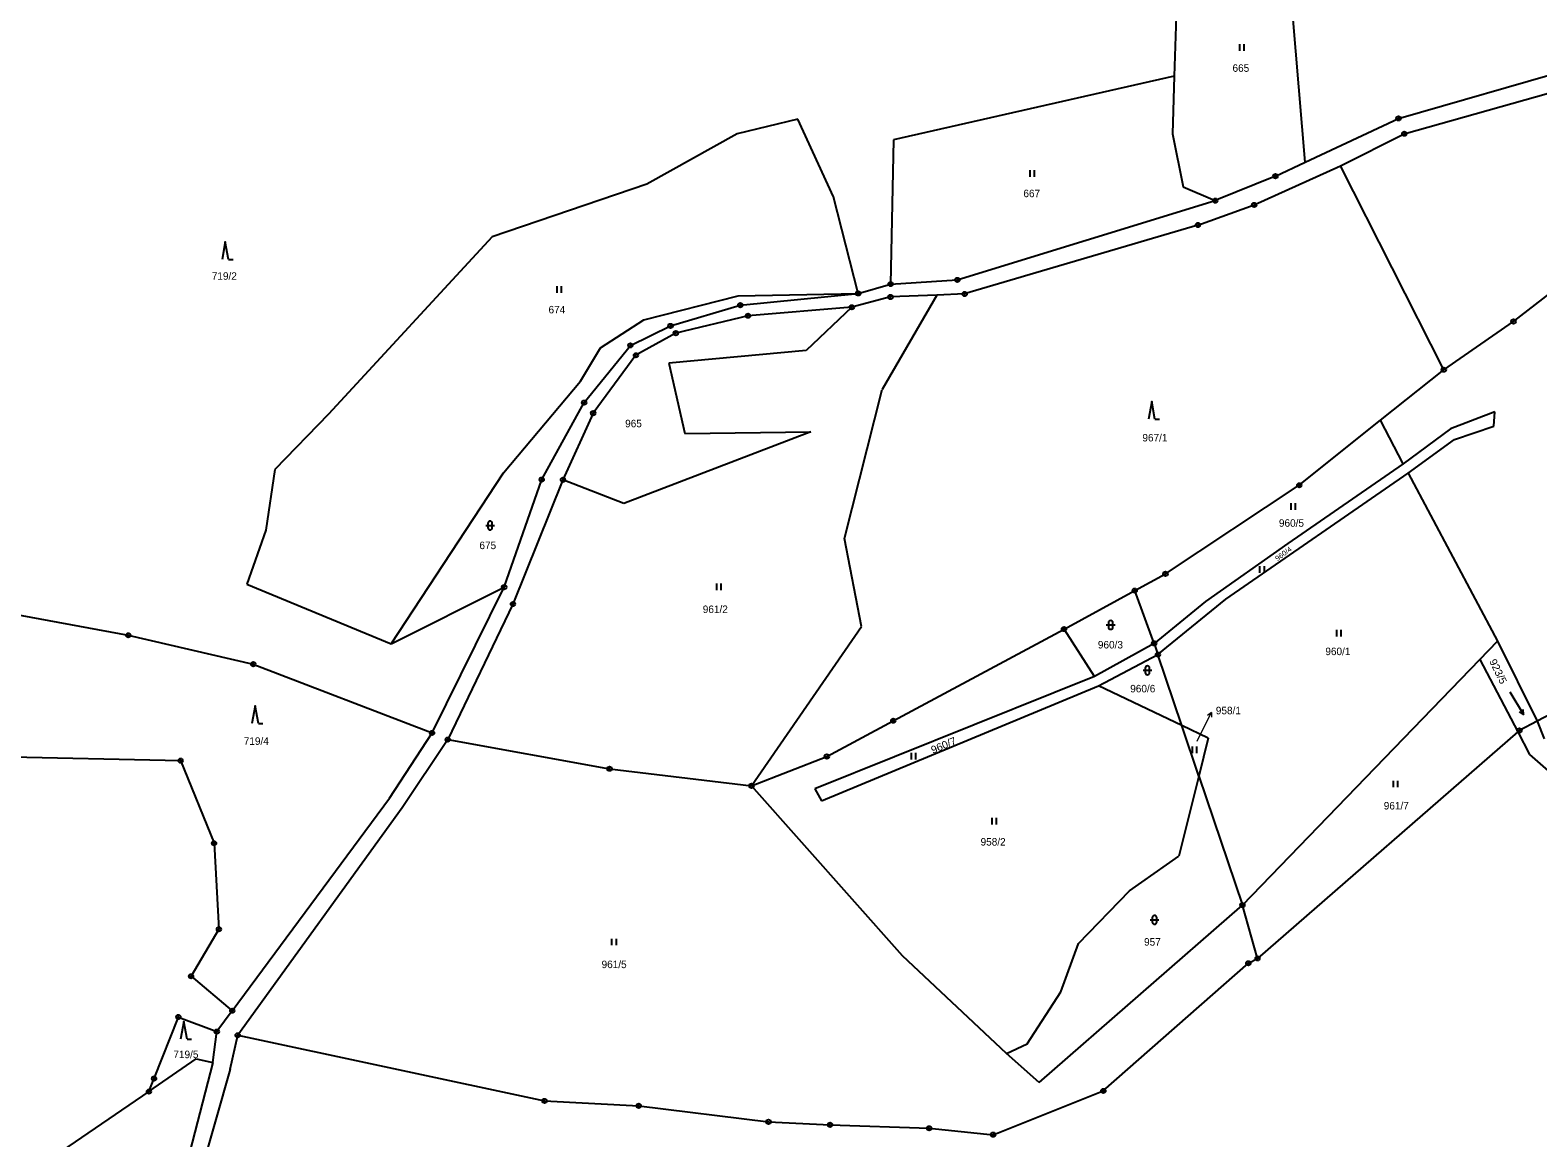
# Model space of a CAD drawing. Extents: x -754970 to -752637, y -970569 to -968179.
# Drawn here: x -753975.6 to -753633.5, y -969678.2 to -969426.8 of the extents above; entities that cross this region are included whole.
import ezdxf
from ezdxf.enums import TextEntityAlignment as Align

# ---------------------------------------------------------------- set-up
doc = ezdxf.new("R2010")
doc.units = 0
doc.header["$LTSCALE"] = 0.68
for name, color, linetype, lineweight in [('1', 7, 'Continuous', 25), ('3', 7, 'Continuous', 25), ('7', 7, 'Continuous', 13), ('8', 7, 'Continuous', 25)]:
    doc.layers.add(name, color=color, linetype=linetype, lineweight=lineweight)
doc.layers.add('2', color=7, linetype='Continuous')

msp = doc.modelspace()

# ---------------------------------------------------------------- linework, layer by layer
at = {"layer": '1'}
for p, q in [((-753714.98, -969405.19), (-753715.98, -969437.31)), ((-753715.98, -969437.31), (-753779.7, -969451.72)), ((-753715.98, -969437.31), (-753716.41, -969450.39)), ((-753665.1, -969446.86), (-753623.7, -969434.99)), ((-753663.79, -969450.36), (-753624.53, -969439.27)), ((-753801.42, -969447.06), (-753815.16, -969450.38)), ((-753793.33, -969464.69), (-753801.42, -969447.06)), ((-753686.27, -969456.81), (-753665.1, -969446.86)), ((-753639, -969492.96), (-753578.22, -969445.91)), ((-753815.16, -969450.38), (-753835.66, -969461.8)), ((-753779.7, -969451.72), (-753780.36, -969484.46)), ((-753716.41, -969450.39), (-753713.98, -969462.36)), ((-753678.26, -969457.64), (-753663.79, -969450.36)), ((-753697.85, -969466.51), (-753678.26, -969457.64)), ((-753654.81, -969503.9), (-753678.26, -969457.64)), ((-753835.66, -969461.8), (-753870.79, -969473.77)), ((-753693.02, -969459.98), (-753706.68, -969465.53)), ((-753787.7, -969486.59), (-753793.33, -969464.69)), ((-753765.21, -969483.51), (-753706.68, -969465.53)), ((-753713.98, -969462.36), (-753706.68, -969465.53)), ((-753710.61, -969471.06), (-753697.85, -969466.51)), ((-753710.61, -969471.06), (-753763.55, -969486.71)), ((-753787.7, -969486.59), (-753780.36, -969484.46)), ((-753780.36, -969484.46), (-753765.21, -969483.51)), ((-753836.36, -969492.55), (-753814.91, -969487.13)), ((-753830.3, -969493.95), (-753814.47, -969489.25)), ((-753814.91, -969487.13), (-753787.7, -969486.59)), ((-753814.47, -969489.25), (-753787.7, -969486.59)), ((-753780.37, -969487.39), (-753789.15, -969489.73)), ((-753769.84, -969486.96), (-753782.28, -969508.37)), ((-753769.84, -969486.96), (-753780.37, -969487.39)), ((-753763.55, -969486.71), (-753769.84, -969486.96)), ((-753846.18, -969498.9), (-753836.36, -969492.55)), ((-753812.69, -969491.66), (-753829.09, -969495.6)), ((-753789.15, -969489.73), (-753812.69, -969491.66)), ((-753789.15, -969489.73), (-753799.5, -969499.54)), ((-753839.39, -969498.38), (-753830.3, -969493.95)), ((-753829.09, -969495.6), (-753838.15, -969500.61)), ((-753654.81, -969503.9), (-753639, -969492.96)), ((-753850.73, -969506.53), (-753846.18, -969498.9)), ((-753849.88, -969511.36), (-753839.39, -969498.38)), ((-753799.5, -969499.54), (-753830.69, -969502.38)), ((-753838.15, -969500.61), (-753847.85, -969513.75)), ((-753830.69, -969502.38), (-753827.05, -969518.38)), ((-753868.2, -969527.28), (-753850.73, -969506.53)), ((-753669.15, -969515.35), (-753654.81, -969503.9)), ((-753790.79, -969542.2), (-753782.28, -969508.37)), ((-753859.51, -969528.82), (-753849.88, -969511.36)), ((-753643.25, -969513.46), (-753653.27, -969517.29)), ((-753643.43, -969516.68), (-753643.25, -969513.46)), ((-753847.85, -969513.75), (-753854.7, -969528.88)), ((-753687.62, -969530.12), (-753669.15, -969515.35)), ((-753664.02, -969525.25), (-753669.15, -969515.35)), ((-753652.42, -969519.72), (-753643.43, -969516.68)), ((-753798.49, -969517.98), (-753840.92, -969534.29)), ((-753827.05, -969518.38), (-753798.49, -969517.98)), ((-753653.27, -969517.29), (-753664.02, -969525.25)), ((-753662.88, -969527.39), (-753652.42, -969519.72)), ((-753920.1, -969526.54), (-753922.09, -969540.28)), ((-753664.02, -969525.25), (-753690.19, -969543.35)), ((-753893.72, -969566.11), (-753868.2, -969527.28)), ((-753868.05, -969553.24), (-753859.51, -969528.82)), ((-753854.7, -969528.88), (-753866.06, -969557.08)), ((-753840.92, -969534.29), (-753854.7, -969528.88)), ((-753717.98, -969550.22), (-753687.62, -969530.12)), ((-753704.29, -969555.98), (-753662.88, -969527.39)), ((-753662.88, -969527.39), (-753642.66, -969565.53)), ((-753922.09, -969540.28), (-753926.41, -969552.59)), ((-753786.94, -969562.16), (-753790.79, -969542.2)), ((-753690.19, -969543.35), (-753708.9, -969556.47)), ((-753724.96, -969554.02), (-753717.98, -969550.22)), ((-753926.41, -969552.59), (-753893.72, -969566.11)), ((-753893.72, -969566.11), (-753868.05, -969553.24)), ((-753884.41, -969586.32), (-753868.05, -969553.24)), ((-753741, -969562.75), (-753724.96, -969554.02)), ((-753720.54, -969565.99), (-753724.96, -969554.02)), ((-753866.06, -969557.08), (-753880.85, -969587.84)), ((-753708.9, -969556.47), (-753720.54, -969565.99)), ((-753719.69, -969568.54), (-753704.29, -969555.98)), ((-753982.52, -969558.79), (-753953.35, -969564.15)), ((-753953.35, -969564.15), (-753924.98, -969570.72)), ((-753811.92, -969598.32), (-753786.94, -969562.16)), ((-753779.75, -969583.55), (-753741, -969562.75)), ((-753734.07, -969573.55), (-753741, -969562.75)), ((-753720.54, -969565.99), (-753734.07, -969573.55)), ((-753720.54, -969565.99), (-753719.69, -969568.54)), ((-753646.62, -969569.63), (-753642.66, -969565.53)), ((-753642.66, -969565.53), (-753633.66, -969583.65)), ((-753924.98, -969570.72), (-753884.41, -969586.32)), ((-753714.26, -969584.64), (-753719.69, -969568.54)), ((-753700.51, -969625.39), (-753646.62, -969569.63)), ((-753646.62, -969569.63), (-753638.02, -969586.07)), ((-753734.07, -969573.55), (-753743.34, -969577.24)), ((-753743.34, -969577.24), (-753797.55, -969598.98)), ((-753742.08, -969579.31), (-753733.17, -969575.62)), ((-753796.05, -969601.72), (-753742.08, -969579.31)), ((-753624.67, -969578.93), (-753633.66, -969583.65)), ((-753794.82, -969591.67), (-753779.75, -969583.55)), ((-753710.39, -969596.11), (-753714.26, -969584.64)), ((-753708.26, -969587.5), (-753714.26, -969584.64)), ((-753633.66, -969583.65), (-753637.65, -969585.74)), ((-753633.66, -969583.65), (-753632.03, -969587.66)), ((-753894.03, -969601.16), (-753884.41, -969586.32)), ((-753880.85, -969587.84), (-753891.2, -969603.3)), ((-753880.85, -969587.84), (-753844.13, -969594.46)), ((-753708.26, -969587.5), (-753710.39, -969596.11)), ((-753638.02, -969586.07), (-753697.07, -969637.48)), ((-753637.65, -969585.74), (-753638.02, -969586.07)), ((-753638.02, -969586.07), (-753635.34, -969591.2)), ((-753988.96, -969591.55), (-753941.47, -969592.61)), ((-753811.92, -969598.32), (-753794.82, -969591.67)), ((-753635.34, -969591.2), (-753597.49, -969624.72)), ((-753941.47, -969592.61), (-753933.87, -969611.36)), ((-753844.13, -969594.46), (-753811.92, -969598.32)), ((-753777.67, -969636.91), (-753811.92, -969598.32)), ((-753797.55, -969598.98), (-753796.05, -969601.72)), ((-753710.39, -969596.11), (-753714.91, -969614.31)), ((-753710.39, -969596.11), (-753700.51, -969625.39)), ((-753929.74, -969649.37), (-753894.03, -969601.16)), ((-753891.2, -969603.3), (-753928.51, -969654.93)), ((-753933.87, -969611.36), (-753932.78, -969630.88)), ((-753726.11, -969622.18), (-753714.91, -969614.31)), ((-753737.7, -969634.14), (-753726.11, -969622.18)), ((-753746.64, -969665.62), (-753700.51, -969625.39)), ((-753697.07, -969637.48), (-753700.51, -969625.39)), ((-753932.78, -969630.88), (-753939.09, -969641.54)), ((-753741.72, -969645.09), (-753737.7, -969634.14)), ((-753754.04, -969659.07), (-753777.67, -969636.91)), ((-753732.08, -969667.57), (-753699.17, -969638.58)), ((-753699.17, -969638.58), (-753697.07, -969637.48)), ((-753939.09, -969641.54), (-753929.74, -969649.37)), ((-753749.35, -969656.88), (-753741.72, -969645.09)), ((-753929.74, -969649.37), (-753933.24, -969654.09)), ((-753947.49, -969664.75), (-753941.97, -969650.79)), ((-753941.97, -969650.79), (-753933.24, -969654.09)), ((-753934.17, -969661.09), (-753933.24, -969654.09)), ((-753930.19, -969662.62), (-753928.51, -969654.93)), ((-753928.51, -969654.93), (-753858.88, -969669.83)), ((-753754.04, -969659.07), (-753749.35, -969656.88)), ((-753948.66, -969667.72), (-753937.9, -969660.29)), ((-753937.9, -969660.29), (-753934.17, -969661.09)), ((-753746.64, -969665.62), (-753754.04, -969659.07)), ((-753934.17, -969661.09), (-753943.76, -969698.49)), ((-753930.19, -969662.62), (-753940.89, -969699.78)), ((-753948.66, -969667.72), (-753947.49, -969664.75)), ((-753948.66, -969667.72), (-753971.56, -969683.36)), ((-753858.88, -969669.83), (-753837.51, -969670.94)), ((-753757.07, -969677.49), (-753732.08, -969667.57)), ((-753837.51, -969670.94), (-753808.06, -969674.58)), ((-753808.06, -969674.58), (-753794.08, -969675.25)), ((-753794.08, -969675.25), (-753771.6, -969676.04)), ((-753771.6, -969676.04), (-753757.07, -969677.49))]:
    msp.add_line(p, q, dxfattribs=at)
for points in [[(-753693.02, -969459.98), (-753686.27, -969456.81), (-753689.84, -969414.44)], [(-753870.79, -969473.77), (-753907.91, -969514.02), (-753920.1, -969526.54)], [(-753714.26, -969584.64), (-753733.17, -969575.62), (-753719.69, -969568.54)]]:
    msp.add_lwpolyline(points, dxfattribs=at)
at = {"layer": '3'}
for p, q in [((-753701.141, -969431.51), (-753701.141, -969430.01)), ((-753700.14, -969431.51), (-753700.14, -969430.01)), ((-753748.681, -969460.13), (-753748.681, -969458.63)), ((-753747.68, -969460.13), (-753747.68, -969458.63)), ((-753930.57, -969478.88), (-753929.574, -969478.88)), ((-753856.031, -969486.43), (-753856.031, -969484.93)), ((-753855.03, -969486.43), (-753855.03, -969484.93)), ((-753720.36, -969515.11), (-753719.364, -969515.11)), ((-753689.451, -969535.68), (-753689.451, -969534.18)), ((-753688.45, -969535.68), (-753688.45, -969534.18)), ((-753872.231, -969539.241), (-753870.229, -969539.241)), ((-753871.731, -969538.741), (-753871.731, -969539.742)), ((-753870.729, -969539.742), (-753870.729, -969538.741)), ((-753696.531, -969549.99), (-753696.531, -969548.49)), ((-753695.53, -969549.99), (-753695.53, -969548.49)), ((-753819.791, -969553.89), (-753819.791, -969552.39)), ((-753818.79, -969553.89), (-753818.79, -969552.39)), ((-753730.911, -969561.311), (-753730.911, -969562.312)), ((-753729.909, -969562.312), (-753729.909, -969561.311)), ((-753731.411, -969561.811), (-753729.409, -969561.811)), ((-753679.091, -969564.45), (-753679.091, -969562.95)), ((-753678.09, -969564.45), (-753678.09, -969562.95)), ((-753722.571, -969571.611), (-753722.571, -969572.612)), ((-753721.569, -969572.612), (-753721.569, -969571.611)), ((-753723.071, -969572.111), (-753721.069, -969572.111)), ((-753636.713, -969582.131), (-753637.646, -969581.551)), ((-753923.81, -969584.17), (-753922.814, -969584.17)), ((-753775.611, -969592.35), (-753775.611, -969590.85)), ((-753774.61, -969592.35), (-753774.61, -969590.85)), ((-753711.841, -969590.9), (-753711.841, -969589.4)), ((-753710.84, -969590.9), (-753710.84, -969589.4)), ((-753666.241, -969598.66), (-753666.241, -969597.16)), ((-753665.24, -969598.66), (-753665.24, -969597.16)), ((-753757.301, -969607.12), (-753757.301, -969605.62)), ((-753756.3, -969607.12), (-753756.3, -969605.62)), ((-753721.461, -969628.731), (-753719.459, -969628.731)), ((-753720.961, -969628.231), (-753720.961, -969629.232)), ((-753719.959, -969629.232), (-753719.959, -969628.231)), ((-753843.581, -969634.52), (-753843.581, -969633.02)), ((-753842.58, -969634.52), (-753842.58, -969633.02)), ((-753939.96, -969655.8), (-753938.964, -969655.8))]:
    msp.add_line(p, q, dxfattribs=at)
for points in [[(-753930.57, -969478.88), (-753931.32, -969474.88), (-753932.07, -969478.88)], [(-753720.36, -969515.11), (-753721.11, -969511.11), (-753721.86, -969515.11)], [(-753639.804, -969576.988), (-753636.713, -969582.131), (-753636.787, -969581.035)], [(-753923.81, -969584.17), (-753924.56, -969580.17), (-753925.31, -969584.17)], [(-753939.96, -969655.8), (-753940.71, -969651.8), (-753941.46, -969655.8)]]:
    msp.add_lwpolyline(points, dxfattribs=at)
for centre, start, end in [((-753871.23, -969538.7409), 0, 180), ((-753871.23, -969539.7409), 180, 359.98789), ((-753730.41, -969561.3109), 0, 180), ((-753730.41, -969562.3109), 180, 359.98789), ((-753722.07, -969571.6109), 0, 180), ((-753722.07, -969572.6109), 180, 359.98789), ((-753720.46, -969628.2309), 0, 180), ((-753720.46, -969629.2309), 180, 359.98789)]:
    msp.add_arc(centre, 0.5, start, end, dxfattribs=at)
at = {"layer": '7'}
msp.add_line((-753707.554, -969581.653), (-753708.444, -969582.333), dxfattribs=at)
msp.add_lwpolyline([(-753710.76, -969588.2), (-753708.87, -969584.35), (-753707.554, -969581.653), (-753707.543, -969582.772)], dxfattribs=at)
at = {"layer": '8'}
for centre, radius in [((-753665.1, -969446.8599), 0.5), ((-753665.1, -969446.8599), 0.0303), ((-753663.79, -969450.3599), 0.5), ((-753663.79, -969450.3599), 0.0303), ((-753693.02, -969459.9799), 0.5), ((-753693.02, -969459.9799), 0.0303), ((-753706.68, -969465.5299), 0.5), ((-753706.68, -969465.5299), 0.0303), ((-753697.85, -969466.5099), 0.5), ((-753697.85, -969466.5099), 0.0303), ((-753710.61, -969471.0599), 0.5), ((-753710.61, -969471.0599), 0.0303), ((-753787.7, -969486.5899), 0.5), ((-753780.36, -969484.4599), 0.5), ((-753780.36, -969484.4599), 0.0303), ((-753765.21, -969483.5099), 0.5), ((-753765.21, -969483.5099), 0.0303), ((-753814.47, -969489.2499), 0.5), ((-753814.47, -969489.2499), 0.0303), ((-753789.15, -969489.7299), 0.5), ((-753787.7, -969486.5899), 0.0303), ((-753780.37, -969487.3899), 0.5), ((-753780.37, -969487.3899), 0.0303), ((-753763.55, -969486.7099), 0.5), ((-753763.55, -969486.7099), 0.0303), ((-753812.69, -969491.6599), 0.5), ((-753812.69, -969491.6599), 0.0303), ((-753789.15, -969489.7299), 0.0303), ((-753639, -969492.9599), 0.5), ((-753639, -969492.9599), 0.0303), ((-753830.3, -969493.9499), 0.5), ((-753830.3, -969493.9499), 0.0303), ((-753829.09, -969495.5999), 0.5), ((-753829.09, -969495.5999), 0.0303), ((-753839.39, -969498.3799), 0.5), ((-753839.39, -969498.3799), 0.0303), ((-753838.15, -969500.6099), 0.5), ((-753838.15, -969500.6099), 0.0303), ((-753654.81, -969503.8999), 0.5), ((-753654.81, -969503.8999), 0.0303), ((-753849.88, -969511.3599), 0.5), ((-753849.88, -969511.3599), 0.0303), ((-753847.85, -969513.7499), 0.5), ((-753847.85, -969513.7499), 0.0303), ((-753859.51, -969528.8199), 0.5), ((-753859.51, -969528.8199), 0.0303), ((-753854.7, -969528.8799), 0.5), ((-753854.7, -969528.8799), 0.0303), ((-753687.62, -969530.1199), 0.5), ((-753687.62, -969530.1199), 0.0303), ((-753717.98, -969550.2199), 0.5), ((-753717.98, -969550.2199), 0.0303), ((-753868.05, -969553.2399), 0.5), ((-753868.05, -969553.2399), 0.0303), ((-753724.96, -969554.0199), 0.5), ((-753724.96, -969554.0199), 0.0303), ((-753866.06, -969557.0799), 0.5), ((-753866.06, -969557.0799), 0.0303), ((-753953.35, -969564.1499), 0.5), ((-753953.35, -969564.1499), 0.0303), ((-753741, -969562.7499), 0.5), ((-753741, -969562.7499), 0.0303), ((-753720.54, -969565.9899), 0.5), ((-753720.54, -969565.9899), 0.0303), ((-753719.69, -969568.5399), 0.5), ((-753924.98, -969570.7199), 0.5), ((-753924.98, -969570.7199), 0.0303), ((-753719.69, -969568.5399), 0.0303), ((-753779.75, -969583.5499), 0.5), ((-753779.75, -969583.5499), 0.0303), ((-753637.65, -969585.7399), 0.5), ((-753884.41, -969586.3199), 0.5), ((-753884.41, -969586.3199), 0.0303), ((-753880.85, -969587.8399), 0.5), ((-753880.85, -969587.8399), 0.0303), ((-753637.65, -969585.7399), 0.0303), ((-753941.47, -969592.6099), 0.5), ((-753794.82, -969591.6699), 0.5), ((-753794.82, -969591.6699), 0.0303), ((-753941.47, -969592.6099), 0.0303), ((-753844.13, -969594.4599), 0.5), ((-753844.13, -969594.4599), 0.0303), ((-753811.92, -969598.3199), 0.5), ((-753811.92, -969598.3199), 0.0303), ((-753933.87, -969611.3599), 0.5), ((-753933.87, -969611.3599), 0.0303), ((-753700.51, -969625.3899), 0.5), ((-753700.51, -969625.3899), 0.0303), ((-753932.78, -969630.8799), 0.5), ((-753932.78, -969630.8799), 0.0303), ((-753699.17, -969638.5799), 0.5), ((-753699.17, -969638.5799), 0.0303), ((-753697.07, -969637.4799), 0.5), ((-753697.07, -969637.4799), 0.0303), ((-753939.09, -969641.5399), 0.5), ((-753939.09, -969641.5399), 0.0303), ((-753941.97, -969650.7899), 0.5), ((-753929.74, -969649.3699), 0.5), ((-753929.74, -969649.3699), 0.0303), ((-753941.97, -969650.7899), 0.0303), ((-753933.24, -969654.0899), 0.5), ((-753933.24, -969654.0899), 0.0303), ((-753928.51, -969654.9299), 0.5), ((-753928.51, -969654.9299), 0.0303), ((-753948.66, -969667.7199), 0.5), ((-753947.49, -969664.7499), 0.5), ((-753947.49, -969664.7499), 0.0303), ((-753732.08, -969667.5699), 0.5), ((-753948.66, -969667.7199), 0.0303), ((-753858.88, -969669.8299), 0.5), ((-753858.88, -969669.8299), 0.0303), ((-753837.51, -969670.9399), 0.5), ((-753732.08, -969667.5699), 0.0303), ((-753837.51, -969670.9399), 0.0303), ((-753808.06, -969674.5799), 0.5), ((-753808.06, -969674.5799), 0.0303), ((-753794.08, -969675.2499), 0.5), ((-753794.08, -969675.2499), 0.0303), ((-753771.6, -969676.0399), 0.5), ((-753771.6, -969676.0399), 0.0303), ((-753757.07, -969677.4899), 0.5), ((-753757.07, -969677.4899), 0.0303)]:
    msp.add_circle(centre, radius, dxfattribs=at)

# ---------------------------------------------------------------- texts
at = {"layer": '2'}
for s, p in [('665', (-753700.869, -969436.295)), ('667', (-753748.319, -969464.745)), ('719/2', (-753931.54, -969483.485)), ('674', (-753856.079, -969491.115)), ('965', (-753838.689, -969516.955)), ('967/1', (-753720.37, -969520.175)), ('960/5', (-753689.39, -969539.535)), ('675', (-753871.759, -969544.615)), ('961/2', (-753820.13, -969559.105)), ('960/3', (-753730.47, -969567.155)), ('960/1', (-753678.85, -969568.665)), ('960/6', (-753723.13, -969577.115)), ('719/4', (-753924.29, -969589.025)), ('961/7', (-753665.6, -969603.695)), ('958/2', (-753757.09, -969611.885)), ('957', (-753720.939, -969634.595)), ('961/5', (-753843.09, -969639.695)), ('719/5', (-753940.26, -969660.125))]:
    msp.add_text(s, height=1.7, dxfattribs=at).set_placement(p, align=Align.CENTER)
for s, height, rotation, width, p in [('960/4', 1.14, 37, 1.1, (-753690.8935, -969546.1059)), ('923/5', 1.7, 296, 1.05, (-753643.2494, -969572.7354)), ('960/7', 1.7, 23, 1.05, (-753768.0041, -969589.909))]:
    msp.add_text(s, height=height, rotation=rotation, dxfattribs=dict(at, width=width)).set_placement(p, align=Align.CENTER)
msp.add_text('958/1', height=1.7, dxfattribs=at).set_placement((-753706.55, -969582.085))

doc.saveas('drawing.dxf')
